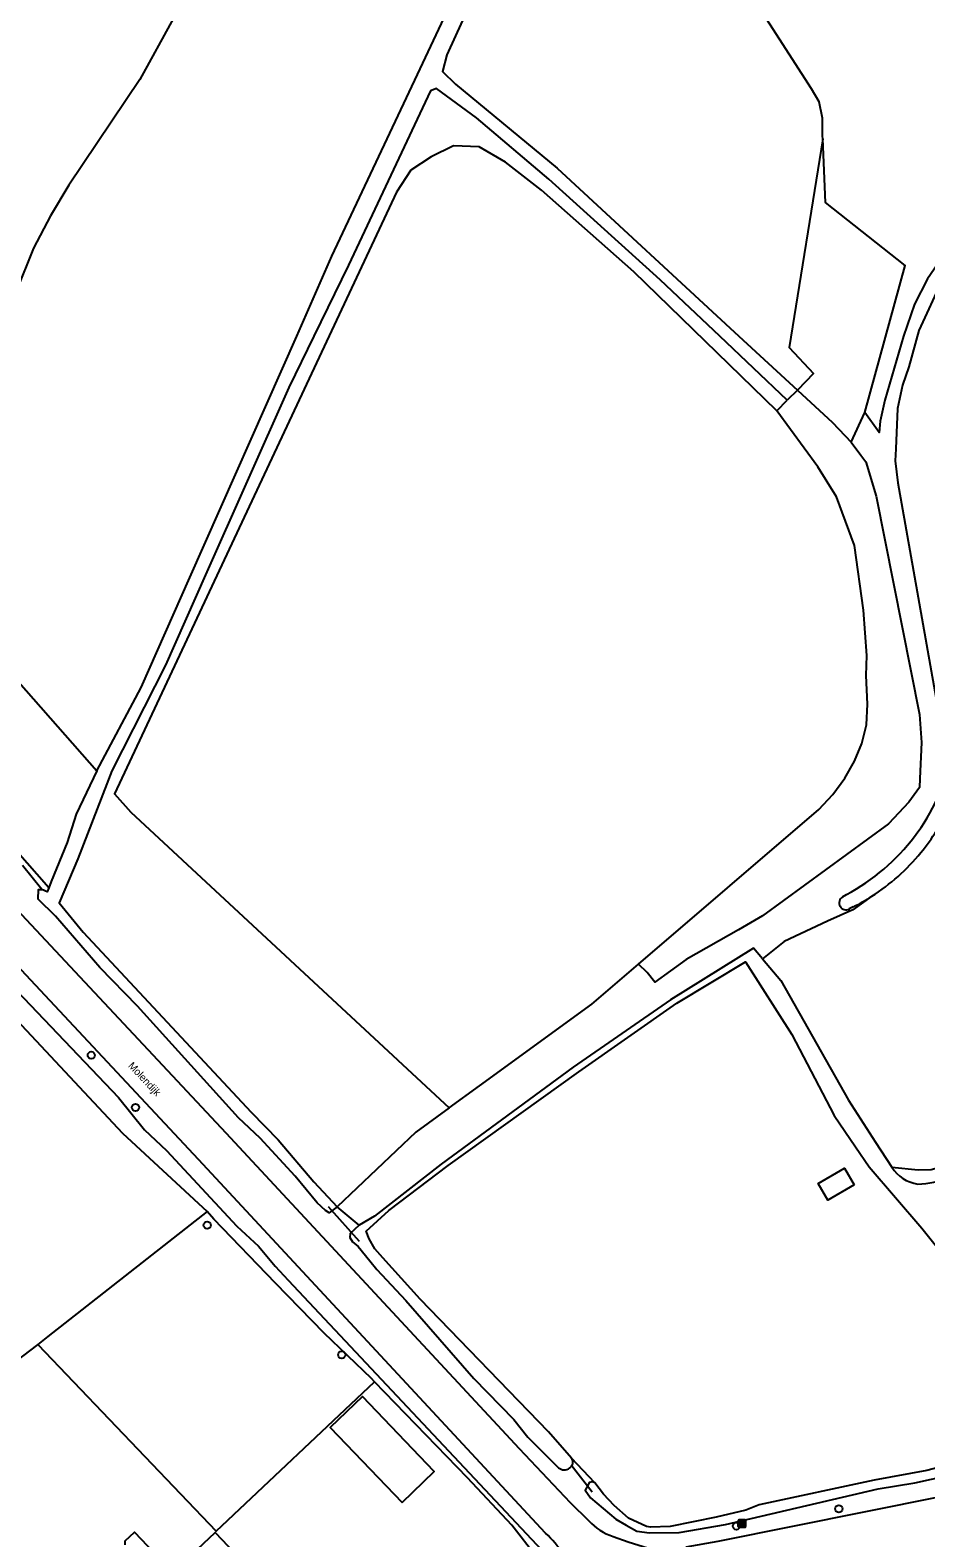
# Model space of a CAD drawing. Extents: x 164494 to 166241, y 382475 to 384494.
# Drawn here: x 165323.6 to 165444.2, y 384088.3 to 384291.2 of the extents above; entities that cross this region are included whole.
import ezdxf

# ---------------------------------------------------------------- set-up
doc = ezdxf.new("R2010")
doc.units = 0
for name, color, linetype in [('IMGEO_Boom', 7, 'Continuous'), ('IMGEO_Bouwland', 7, 'Continuous'), ('IMGEO_Duiker', 7, 'Continuous'), ('IMGEO_Grasland_agrarisch', 7, 'Continuous'), ('IMGEO_Grasland_overig', 7, 'Continuous'), ('IMGEO_Groenvoorziening', 7, 'Continuous'), ('IMGEO_Loofbos', 7, 'Continuous'), ('IMGEO_Openbare_ruimte_label', 7, 'Continuous'), ('IMGEO_Pand', 7, 'Continuous'), ('IMGEO_Rijbaan_lokaal_gesloten', 7, 'Continuous'), ('IMGEO_Waterloop', 7, 'Continuous'), ('IMGEO_Wegwijzer', 7, 'Continuous')]:
    doc.layers.add(name, color=color, linetype=linetype)

msp = doc.modelspace()

# ---------------------------------------------------------------- linework, layer by layer
at = {"layer": 'IMGEO_Boom'}
for centre in [(165331.79, 384153.21), (165337.74, 384146.19), (165347.4, 384130.34), (165365.51, 384112.88), (165432.45, 384092.16), (165418.65, 384089.84)]:
    msp.add_circle(centre, 0.489, dxfattribs=at)
at = {"layer": 'IMGEO_Bouwland'}
msp.add_lwpolyline([(165424.11, 384239.93), (165404.83, 384258.64), (165392.42, 384269.63), (165387.55, 384273.42), (165384.03, 384275.46), (165380.58, 384275.62), (165377.55, 384274.13), (165374.81, 384272.33), (165372.87, 384269.39), (165334.92, 384188.38), (165337.12, 384185.91), (165379.98, 384146.12)], dxfattribs=at)
at = {"layer": 'IMGEO_Duiker'}
for points in [[(165367.89, 384128.14), (165363.75, 384132.82)], [(165399.24, 384094.41), (165396.41, 384098.05)]]:
    msp.add_lwpolyline(points, dxfattribs=at)
at = {"layer": 'IMGEO_Grasland_agrarisch'}
for points in [[(165430.28, 384276.54), (165425.76, 384248.48), (165429.02, 384244.97), (165426.88, 384242.71)], [(165347.39, 384132.2), (165325.92, 384115.35), (165324.58, 384114.29)], [(165324.58, 384114.29), (165317.6, 384108.97), (165252.15, 384058.98)]]:
    msp.add_lwpolyline(points, dxfattribs=at)
at = {"layer": 'IMGEO_Grasland_overig'}
for points in [[(165326.06, 384175.76), (165321.54, 384180.91), (165316.39, 384186.25), (165293.19, 384211.49), (165251.87, 384255.44), (165233.08, 384275.18)], [(165434.09, 384235.72), (165435.96, 384239.72)], [(165439.58, 384138.15), (165443.14, 384137.77), (165444.87, 384137.84), (165446.85, 384138.39), (165448.47, 384139.12), (165455.48, 384145.52), (165460.29, 384150.96), (165467.36, 384159.23), (165480.29, 384177.58), (165497.03, 384199.38), (165497.99, 384201.63), (165497.95, 384203.22), (165497.56, 384205.09), (165477.73, 384217.77), (165475.07, 384217.77), (165472.61, 384217.34), (165461.02, 384205.38)], [(165325.13, 384175.54), (165322.53, 384178.74)], [(165436.89, 384174.61), (165434.35, 384172.79), (165430.94, 384171.27), (165425.08, 384168.54), (165422.16, 384166.2)], [(165379.98, 384146.12), (165384.07, 384149.1), (165399.2, 384160.09), (165405.48, 384165.47)], [(165379.98, 384146.12), (165375.51, 384142.87), (165364.91, 384132.82)], [(165367.85, 384130.32), (165364.91, 384132.82)]]:
    msp.add_lwpolyline(points, dxfattribs=at)
at = {"layer": 'IMGEO_Groenvoorziening'}
msp.add_lwpolyline([(165324.58, 384114.29), (165348.61, 384089.13), (165369.93, 384109.25)], dxfattribs=at)
at = {"layer": 'IMGEO_Loofbos'}
for points in [[(165384.15, 384416.68), (165385.18, 384417.99), (165396.48, 384398.38), (165397.15, 384397.09), (165396.94, 384395.72), (165381.32, 384364.2), (165365.49, 384336.67), (165349.35, 384306.46), (165349.05, 384305.91), (165342.87, 384292.8), (165338.34, 384284.53), (165328.75, 384270.31), (165326.28, 384266.2), (165323.99, 384261.84), (165319.21, 384250), (165316.17, 384243.24), (165305.04, 384222.67), (165310.21, 384216.8), (165313.46, 384213.11), (165332.53, 384191.47)], [(165430.28, 384276.54), (165430.27, 384276.93), (165430.27, 384279.34), (165429.82, 384281.52), (165428.75, 384283.28), (165407.63, 384316.14), (165398.91, 384331.4)], [(165435.96, 384239.72), (165441.4, 384259.53), (165430.64, 384267.98), (165430.28, 384276.54)], [(165455.14, 384266.36), (165450.12, 384264.28), (165447.08, 384261.62), (165444.39, 384257.73), (165442.66, 384254.31), (165441.17, 384250), (165438.63, 384241.4), (165438.03, 384238.56), (165437.86, 384237.01), (165435.96, 384239.72)], [(165446.4, 384257.65), (165443.2, 384250.74), (165441.86, 384245.86), (165441.02, 384243.4), (165440.33, 384240.27), (165440.11, 384234.82), (165440.05, 384233.22), (165440.39, 384230.27), (165447.01, 384193.06)], [(165426.88, 384242.71), (165431.58, 384238.36), (165434.09, 384235.72)], [(165424.11, 384239.93), (165425.5, 384241.39)], [(165405.48, 384165.47), (165429.76, 384186.27), (165431.64, 384188.29), (165433.24, 384190.5), (165434.54, 384192.78), (165435.53, 384195.19), (165436.17, 384197.7), (165436.33, 384200.45), (165436.11, 384204.33), (165436.22, 384207.03), (165435.75, 384213.14), (165434.56, 384221.8), (165432.13, 384228.39), (165429.6, 384232.39), (165424.11, 384239.93)], [(165434.09, 384235.72), (165435.41, 384233.97), (165436.07, 384233.1), (165437.46, 384228.45), (165443.33, 384199.09), (165443.58, 384195.3), (165443.37, 384190.46), (165443.32, 384189.24), (165441.87, 384187.26), (165439.12, 384184.34), (165422.17, 384171.96), (165418.92, 384170.1), (165411.88, 384166.09), (165407.66, 384163.04), (165406.62, 384164.33), (165405.48, 384165.47)], [(165399.6, 384095.65), (165396.43, 384098.96)]]:
    msp.add_lwpolyline(points, dxfattribs=at)
at = {"layer": 'IMGEO_Pand'}
for points in [[(165434.53, 384135.76), (165430.95, 384133.69), (165429.65, 384135.93), (165433.23, 384138), (165434.53, 384135.76)], [(165373.63, 384093), (165377.97, 384097.16), (165368.29, 384107.26), (165363.95, 384103.1), (165373.63, 384093)], [(165336.34, 384087.33), (165336.36, 384087.85), (165337.61, 384089.03), (165342.75, 384083.58)], [(165342.75, 384083.58), (165345.33, 384086.01), (165348.49, 384088.99), (165354.51, 384082.6), (165345.26, 384073.88), (165339.24, 384080.26), (165341.07, 384081.99)]]:
    msp.add_lwpolyline(points, dxfattribs=at)
at = {"layer": 'IMGEO_Rijbaan_lokaal_gesloten'}
for points in [[(165266.44, 384231.9), (165272.49, 384225.43), (165349.9, 384142.75), (165389.4, 384100.28), (165396.29, 384093.01), (165398.79, 384090.55)], [(165392.96, 384088.88), (165346.21, 384139.18), (165268.81, 384221.91), (165262.69, 384228.45)], [(165411.91, 384087.02), (165416.2, 384087.82), (165455.96, 384095.8)], [(165402.07, 384088.45), (165404.09, 384087.71), (165406.82, 384086.87)]]:
    msp.add_lwpolyline(points, dxfattribs=at)
for centre, radius, start, end in [((165404.21, 384095.39), 7.27, 221.7665, 252.7984), ((165378.23, 384073.55), 21.26, 36.212, 46.1394)]:
    msp.add_arc(centre, radius, start, end, dxfattribs=at)
at = {"layer": 'IMGEO_Waterloop'}
for points in [[(165332.53, 384191.47), (165338.52, 384202.73), (165345.06, 384217.5), (165359.45, 384250), (165364.2, 384260.75), (165375.7, 384285.21), (165392.98, 384321.96), (165397.13, 384331.86), (165398.91, 384331.4)], [(165398.91, 384331.4), (165397, 384326.87), (165391.37, 384313.56), (165379.68, 384287.88), (165379.09, 384285.64), (165380.81, 384283.93), (165394.5, 384272.63), (165418.99, 384250), (165426.88, 384242.71)], [(165425.5, 384241.39), (165416.42, 384250), (165408.4, 384257.6), (165393.38, 384271.14), (165383.68, 384279.39), (165378.26, 384283.35), (165377.45, 384283.01), (165366.44, 384259.54), (165361.77, 384250), (165358.39, 384243.09), (165347.17, 384217.89), (165341.76, 384205.72), (165334.57, 384191.51), (165333.88, 384189.72), (165329.97, 384179.63), (165327.44, 384173.72), (165330.68, 384169.78), (165353.31, 384145.55), (165356.95, 384141.82), (165361.77, 384136.17), (165364.91, 384132.82)], [(165426.88, 384242.71), (165425.5, 384241.39)], [(165332.53, 384191.47), (165329.77, 384185.67), (165328.54, 384181.84), (165326.4, 384176.6), (165326.06, 384175.76)], [(165364.91, 384132.82), (165364.37, 384132.41), (165363.83, 384132.01), (165363.31, 384132.3), (165362.22, 384133.36), (165359.22, 384136.93), (165354.53, 384142.04), (165351.59, 384144.78), (165338.02, 384159.8), (165332.93, 384165.02), (165326.97, 384171.93), (165324.64, 384174.2), (165324.69, 384175.5), (165325.13, 384175.54)], [(165326.06, 384175.76), (165325.83, 384175.2), (165325.13, 384175.54)], [(165432.93, 384174.51), (165433.48, 384174.84)], [(165434.39, 384173.18), (165433.86, 384172.9)], [(165309.08, 384171.59), (165309.12, 384171.92), (165309.26, 384172.26), (165309.56, 384172.65), (165310.03, 384172.86), (165310.43, 384172.86), (165310.99, 384172.79), (165318.08, 384165.69), (165335.46, 384147.52), (165338.93, 384143.15), (165341.91, 384140.37), (165351.37, 384130.2), (165354.29, 384127.52), (165356.55, 384124.82), (165358.3, 384122.95), (165392.45, 384086.58)], [(165309.08, 384171.59), (165315.88, 384164.36), (165320.44, 384159.32), (165335.97, 384142.71), (165347.39, 384132.2)], [(165422.16, 384166.2), (165420.97, 384167.63), (165409.79, 384160.68), (165396.68, 384151.59), (165378.91, 384138.55), (165369.91, 384131.53), (165367.85, 384130.32)], [(165396.43, 384098.96), (165393.36, 384102.54), (165376.05, 384120.38), (165371.06, 384125.95), (165369.98, 384127.15), (165369.19, 384128.51), (165368.79, 384129.53), (165371.85, 384132.31), (165379.84, 384138.36), (165397.44, 384150.98), (165410.63, 384160.2), (165419.9, 384165.79), (165426.11, 384155.98), (165431.82, 384145.09), (165434.69, 384140.9), (165436.54, 384138.19), (165443.62, 384129.92), (165449.75, 384122.32), (165456.3, 384114.59), (165462.24, 384108.19)], [(165422.16, 384166.2), (165424.62, 384163.25), (165433.76, 384147.17), (165437.4, 384141.53), (165439.58, 384138.15)], [(165369.93, 384109.25), (165369.5, 384109.69), (165363.14, 384115.79), (165356.6, 384122.55), (165348.29, 384131.16), (165347.39, 384132.2)], [(165367.85, 384130.32), (165367.24, 384129.76), (165366.63, 384129.21), (165366.61, 384128.67), (165366.94, 384128.09), (165367.72, 384127.48), (165369.29, 384125.53), (165370.24, 384124.35), (165374.13, 384120.18), (165383.32, 384109.71), (165388.69, 384104.19), (165390.57, 384101.8), (165394.69, 384097.69)], [(165391.68, 384085.73), (165388.41, 384089.95), (165382.45, 384096.31), (165369.93, 384109.25)], [(165399.6, 384095.65), (165399.26, 384095.79), (165398.85, 384095.68), (165398.68, 384095.37), (165398.31, 384094.68), (165399, 384093.66), (165402.44, 384090.75), (165403.83, 384089.96), (165405.25, 384089.15), (165406.97, 384088.92), (165410.95, 384088.97), (165417.21, 384090.03), (165437.75, 384094.84), (165442.7, 384095.67), (165453.48, 384098.05), (165453.39, 384098.62), (165453.31, 384099.19)], [(165453.31, 384099.19), (165451.79, 384098.76), (165449.11, 384098.58), (165444.31, 384097.31), (165437.2, 384096.02), (165421.73, 384092.69), (165419.92, 384091.99), (165415.95, 384091.04), (165409.72, 384089.8), (165407.08, 384089.7), (165406.54, 384089.8), (165404.14, 384090.9), (165402.2, 384092.61), (165400.76, 384094.14), (165399.6, 384095.65)]]:
    msp.add_lwpolyline(points, dxfattribs=at)
for centre, radius, start, end in [((165420.12, 384199.78), 28.29, 298.1787, 347.3156), ((165419.89, 384199.67), 30.42, 320.9325, 334.5586), ((165421.42, 384198.7), 28.63, 302.699, 320.5015), ((165433.43, 384173.72), 0.928, 122.0119, 298.0605), ((165421.25, 384199), 28.97, 296.9833, 302.6649), ((165442.77, 384147.31), 11.44, 271.5337, 315.1976), ((165443.82, 384140.85), 5.03, 212.4222, 261.4402), ((165395.84, 384098.42), 0.797, 311.7674, 42.5734), ((165395.47, 384098.56), 1.16, 228.1885, 308.9226), ((165395.48, 384098.55), 1.15, 308.9744, 321.0256)]:
    msp.add_arc(centre, radius, start, end, dxfattribs=at)
at = {"layer": 'IMGEO_Wegwijzer'}
for p, q in [((165418.91, 384089.78), (165418.91, 384090.58)), ((165418.91, 384090.58), (165418.91, 384089.78)), ((165419.01, 384090.68), (165419.8, 384090.68)), ((165419.8, 384090.68), (165419.01, 384090.68)), ((165419.9, 384090.58), (165419.9, 384089.78)), ((165419.9, 384089.78), (165419.9, 384090.58)), ((165419.8, 384089.68), (165419.01, 384089.68)), ((165419.01, 384089.68), (165419.8, 384089.68))]:
    msp.add_line(p, q, dxfattribs=at)
for points in [[(165419.01, 384090.42), (165419.8, 384090.42), (165419.8, 384089.95), (165419.01, 384089.95), (165419.01, 384090.42)], [(165419.07, 384090.27), (165419.07, 384090.18), (165419.07, 384090.1), (165419.49, 384090.1), (165419.49, 384090.02), (165419.73, 384090.18), (165419.49, 384090.35), (165419.49, 384090.27), (165419.07, 384090.27)]]:
    msp.add_lwpolyline(points, dxfattribs=at)
for centre, start, end in [((165419.01, 384090.58), 90, 180), ((165419.01, 384090.58), 90, 180), ((165419.8, 384090.58), 0, 90), ((165419.8, 384090.58), 360, 90), ((165419.01, 384089.78), 180, 270), ((165419.01, 384089.78), 180, 270), ((165419.8, 384089.78), 270, 0), ((165419.8, 384089.78), 270, 0)]:
    msp.add_arc(centre, 0.1, start, end, dxfattribs=at)

# ---------------------------------------------------------------- texts
at = {"layer": 'IMGEO_Openbare_ruimte_label'}
msp.add_text('Molendijk', height=1, rotation=313.0949, dxfattribs=at).set_placement((165336.68, 384151.73))

doc.saveas('drawing.dxf')
